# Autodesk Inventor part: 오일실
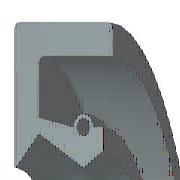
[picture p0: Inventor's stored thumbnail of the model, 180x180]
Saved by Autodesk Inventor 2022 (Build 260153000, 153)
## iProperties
Created: 2021-07
Part Number: 오일실
Material: 고무
Description: 오일-실
Document SubType Name: Modeling
Standard: KS B 2804
Designer: mdu
Standards Organization: KS
Language: ko-KR
Size Designation: D - 10 20 7
Categories: <MemberInstance><Categories><Category DisplayName="샤프트 부품" InternalName="7f7aeb1f-a693-4053-b835-cee3144e0d98" Mnemonic="SHFT"><Category DisplayName="실링" Intern
Density: 0.93 g/cm^3
Mass: 1.11329 g
Surface Area: 16.3871 cm^2
Volume: 1.19708 cm^3
Appearance: 고무 - 검은색 - 버전 1.1
IsCustomPart: 0
Author: mdu
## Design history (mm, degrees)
revolve "본체" stored, may be unused: angle "d17" = 90 deg
revolve "스프링1" stored, may be unused: angle "d18" = 90 deg
body "Solid1"
sketch "스케치1"
  geometry: L1 (0, 10)-(7, 10); L2 (7, 8.25)-(1.75, 8.25); L3 (1.75, 6.75)-(4.9, 5); L4 (4.9, 5)-(0, 5); L5 (0, 0)-(9.586, 0) reference; L6 (4.9, 5)-(6.3, 5.875); L7 (0, 18)-(0, -3) reference; L8 (-1.941, 0)-(11.507, 0) reference; L9 (4.2, 7.1)-(1.75, 7.59); L10 (1.75, 7.59)-(1.75, 8.25); L11 (0, 10)-(0, 5.088); L12 (4.9, 5)-(0, 5); L13 (1.75, 6.75)-(0.152, 5.028); L14 (7, 10)-(7, 8.25); L15 (5.6, 7.1)-(6.3, 7.1); L16 (6.3, 7.1)-(6.3, 5.875); C1 r 0.455 at (4.9, 7.1); A1 r 0.7 centre (4.9, 7.1) between (5.6, 7.1) and (4.2, 7.1); A2 r 0.088 centre (0.088, 5.088) between (0, 5.088) and (0.152, 5.028); 1 further point
  constraints: 28 end point, 5 horizontal alignment, 5 point on line, 4 point on circle, 4 vertical alignment, 3 centre point, 3 tangent, 2 collinear, 2 horizontal, 2 perpendicular, 1 coincident, 1 parallel
  dimensions: "d0" = 20 diameter of L1 L5 (= SD2); "d1" = 1.75 distance of L1.end L2.start (= SD); "d2" = 0.91 diameter of C1 (= SPDI); "d3" = 1.4 diameter of A1 (= SPDA); "d4" = 10 diameter of L3.end L5 (= NND); "d5" = 13.5 diameter of L3.start L5 (= TKDM); "d7" = 15.18 diameter of L9.end L5 (= TKDM + 0.24 x SWDT); "d8" = 1.75 distance between parallel lines of L11 L10 (= SD); "d9" = 4.9 distance from line of L11 C1.centre (= SPDST); "d10" = 14.2 diameter of C1.centre L5 (= HLDM); "d11" = 0.0875 radius of A2 (= 0.25 x LAB); "d12" = 6.3 distance between parallel lines of L11 L16 (= SDI); "d13" = 11.75 diameter of L6.end L5 (= ABDM); "d14" = 7 distance from line of L11 L1.end (= SWDT)
fillet "모깎기1" dims "d6" = 0.3 (= RR)
other parameters: "SD2" = 20 [user parameter; used in 1 equation term], "SWDT" = 7 [user parameter; used in 2 equation terms], "RR" = 0.3 [user parameter; used in 1 equation term], "SD" = 1.75 [user parameter; used in 2 equation terms], "NND" = 10 [user parameter; used in 1 equation term], "SPDA" = 1.4 [user parameter; used in 1 equation term], "SPDI" = 0.91 [user parameter; used in 1 equation term], "TKDM" = 13.5 [user parameter; used in 2 equation terms], "HLDM" = 14.2 [user parameter; used in 1 equation term], "ABDM" = 11.75 [user parameter; used in 1 equation term], "SDI" = 6.3 [user parameter; used in 1 equation term], "SPDST" = 4.9 [user parameter; used in 1 equation term], "LAB" = 0.35 [user parameter; used in 1 equation term], "d15" = 0, "d16" = 0, "d19" = 0
